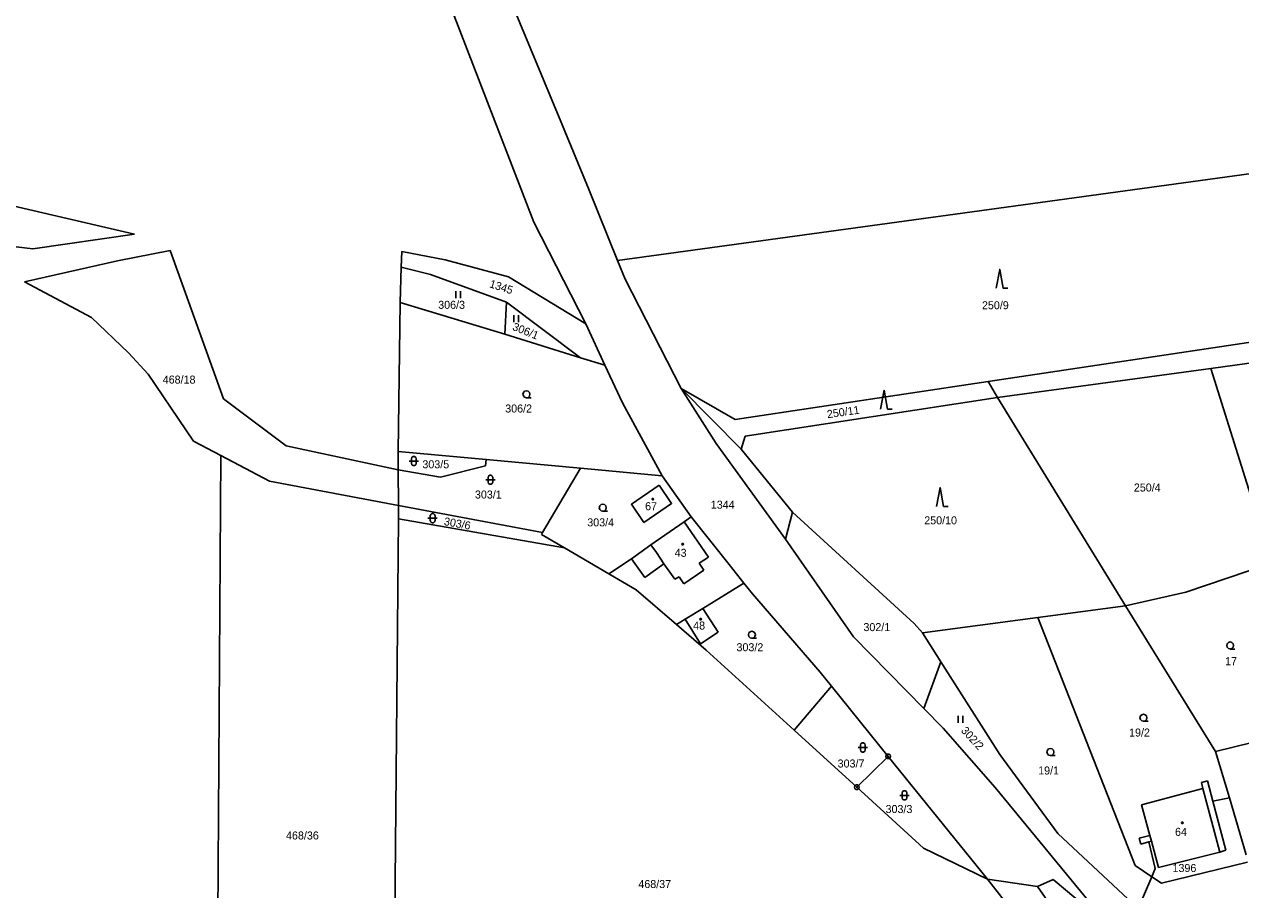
# Model space of a CAD drawing. Extents: x -845995 to -842497, y -1063614 to -1059680.
# Drawn here: x -844799.8 to -844541.5, y -1061389.6 to -1061205.9 of the extents above; entities that cross this region are included whole.
import ezdxf

# ---------------------------------------------------------------- set-up
doc = ezdxf.new("R2010")
doc.units = 0
for name, color, linetype in [('KN_HRANICE', 7, 'Continuous'), ('KN_KULTURY', 7, 'Continuous'), ('KN_MEZNIKY', 7, 'Continuous'), ('KN_PARCELY', 7, 'Continuous'), ('KN_SLUCKY', 7, 'Continuous'), ('KN_STAVEBNI', 7, 'Continuous')]:
    doc.layers.add(name, color=color, linetype=linetype)

# ---------------------------------------------------------------- blocks, each defined once
blk = doc.blocks.new('304')
blk.add_lwpolyline([(0, 0), (-0.38, 0.1), (-0.65, 0.37), (-0.75, 0.74), (-0.65, 1.11), (-0.38, 1.38), (-0.01, 1.48), (0.36, 1.38), (0.63, 1.11), (0.73, 0.73), (0.63, 0.35), (0.36, 0.08), (-0.02, -0.02), (0.98, -0.02)])
blk = doc.blocks.new('306')
for p, q in [((-0.5, 1.5), (-0.5, 0)), ((0.5, 0), (0.5, 1.5))]:
    blk.add_line(p, q)
blk = doc.blocks.new('308')
blk.add_lwpolyline([(-0.75, 0), (0, 4), (0.75, 0), (1.75, 0)])
blk = doc.blocks.new('316')
for points in [[(-1, 1), (0.27, 1), (1, 1)], [(-0.5, 1.5), (-0.4, 1.79), (-0.15, 1.97), (0.16, 1.97), (0.41, 1.79), (0.51, 1.5), (0.51, 0.5), (0.41, 0.21), (0.16, 0.03), (-0.15, 0.03), (-0.4, 0.21), (-0.5, 0.5), (-0.5, 1.5)]]:
    blk.add_lwpolyline(points)
blk = doc.blocks.new('105')
blk.add_line((-0.12, 0), (0.12, 0))
blk.add_lwpolyline([(0.15, 0.48), (0.4, 0.3), (0.5, 0.01), (0.4, -0.28), (0.15, -0.46), (-0.16, -0.46), (-0.41, -0.28), (-0.51, 0.01), (-0.41, 0.3), (-0.16, 0.48), (0.15, 0.48)])
blk = doc.blocks.new('402')
blk.add_lwpolyline([(0.09, 0.15), (0.18, 0), (0.09, -0.15), (-0.09, -0.15), (-0.18, 0), (-0.09, 0.15), (0.09, 0.15)])

msp = doc.modelspace()

# ---------------------------------------------------------------- linework, layer by layer
at = {"layer": 'KN_HRANICE'}
for p, q in [((-844720.73, -1061172.52), (-844691.6, -1061247.89)), ((-844685.56, -1061227.38), (-844703.99, -1061182.85)), ((-844679.88, -1061241.1), (-844685.56, -1061227.38)), ((-844673.82, -1061256.03), (-844523.56, -1061235.4)), ((-844679.88, -1061241.1), (-844673.82, -1061256.03)), ((-844776.42, -1061250.39), (-844804.1, -1061244)), ((-844852.01, -1061247.02), (-844797.97, -1061253.52)), ((-844691.6, -1061247.89), (-844680.59, -1061269.45)), ((-844797.97, -1061253.52), (-844776.42, -1061250.39)), ((-844780.02, -1061256.12), (-844768.84, -1061253.9)), ((-844768.84, -1061253.9), (-844757.5, -1061285.36)), ((-844719.67, -1061254.09), (-844719.77, -1061257.41)), ((-844710.46, -1061255.86), (-844719.67, -1061254.09)), ((-844799.79, -1061260.56), (-844780.02, -1061256.12)), ((-844697.02, -1061259.49), (-844710.46, -1061255.86)), ((-844673.82, -1061256.03), (-844672.21, -1061260)), ((-844719.77, -1061257.41), (-844719.98, -1061264.93)), ((-844713.56, -1061258.96), (-844719.77, -1061257.41)), ((-844697.4, -1061264.85), (-844713.56, -1061258.96)), ((-844680.59, -1061269.45), (-844697.02, -1061259.49)), ((-844785.52, -1061268.09), (-844799.79, -1061260.56)), ((-844672.21, -1061260), (-844660.3, -1061283.17)), ((-844719.98, -1061264.93), (-844720.4, -1061296.53)), ((-844719.98, -1061264.93), (-844697.8, -1061271.68)), ((-844697.4, -1061264.85), (-844697.8, -1061271.68)), ((-844681.7, -1061276.68), (-844697.4, -1061264.85)), ((-844777.71, -1061275.61), (-844785.52, -1061268.09)), ((-844680.59, -1061269.45), (-844676.52, -1061278.21)), ((-844697.8, -1061271.68), (-844681.7, -1061276.68)), ((-844595.18, -1061281.72), (-844522.5, -1061270.83)), ((-844547.89, -1061278.94), (-844509.56, -1061273.56)), ((-844773.47, -1061280.17), (-844777.71, -1061275.61)), ((-844676.52, -1061278.21), (-844681.7, -1061276.68)), ((-844773.47, -1061280.17), (-844763.91, -1061294.34)), ((-844676.52, -1061278.21), (-844672.78, -1061286.23)), ((-844547.89, -1061278.94), (-844593.18, -1061285.1)), ((-844534.95, -1061320.21), (-844547.89, -1061278.94)), ((-844648.86, -1061289.77), (-844595.18, -1061281.72)), ((-844593.18, -1061285.1), (-844595.18, -1061281.72)), ((-844757.5, -1061285.36), (-844744.19, -1061295.34)), ((-844648.86, -1061289.77), (-844660.3, -1061283.17)), ((-844660.3, -1061283.17), (-844647.58, -1061296.05)), ((-844646.76, -1061293.3), (-844593.18, -1061285.1)), ((-844593.18, -1061285.1), (-844565.97, -1061329.33)), ((-844672.78, -1061286.23), (-844664.39, -1061301.73)), ((-844647.58, -1061296.05), (-844646.76, -1061293.3)), ((-844763.91, -1061294.34), (-844758.07, -1061297.42)), ((-844744.19, -1061295.34), (-844720.45, -1061300.43)), ((-844759.29, -1061483.09), (-844758.07, -1061297.42)), ((-844758.07, -1061297.42), (-844747.75, -1061302.86)), ((-844720.45, -1061300.43), (-844720.4, -1061296.53)), ((-844701.72, -1061298.26), (-844720.4, -1061296.53)), ((-844701.87, -1061299.6), (-844701.72, -1061298.26)), ((-844701.72, -1061298.26), (-844681.7, -1061300.12)), ((-844636.7, -1061309.42), (-844647.58, -1061296.05)), ((-844720.45, -1061300.43), (-844711.43, -1061302.02)), ((-844720.45, -1061300.43), (-844720.38, -1061308)), ((-844711.43, -1061302.02), (-844701.87, -1061299.6)), ((-844681.7, -1061300.12), (-844689.75, -1061313.76)), ((-844681.7, -1061300.12), (-844664.39, -1061301.73)), ((-844747.75, -1061302.86), (-844720.38, -1061308)), ((-844664.39, -1061301.73), (-844658.2, -1061310.45)), ((-844720.38, -1061308), (-844720.36, -1061310.83)), ((-844720.38, -1061308), (-844689.75, -1061313.76)), ((-844720.36, -1061310.83), (-844721.83, -1061477.08)), ((-844720.36, -1061310.83), (-844685.12, -1061317)), ((-844659.68, -1061311.49), (-844666.75, -1061316.38)), ((-844659.68, -1061311.49), (-844658.2, -1061310.45)), ((-844650.16, -1061320.55), (-844658.2, -1061310.45)), ((-844636.7, -1061309.42), (-844638.21, -1061315.18)), ((-844610.86, -1061333.04), (-844636.7, -1061309.42)), ((-844689.75, -1061313.76), (-844689.98, -1061314.15)), ((-844685.12, -1061317), (-844689.98, -1061314.15)), ((-844670.88, -1061319.31), (-844666.75, -1061316.38)), ((-844638.21, -1061315.18), (-844623.75, -1061335.89)), ((-844675.67, -1061322.54), (-844685.12, -1061317)), ((-844675.67, -1061322.54), (-844670.88, -1061319.31)), ((-844646.99, -1061324.49), (-844650.16, -1061320.55)), ((-844553.2, -1061326.42), (-844534.95, -1061320.21)), ((-844669.9, -1061325.92), (-844675.67, -1061322.54)), ((-844661.35, -1061333.29), (-844669.9, -1061325.92)), ((-844655.73, -1061329.85), (-844646.99, -1061324.49)), ((-844645.22, -1061326.74), (-844646.99, -1061324.49)), ((-844645.22, -1061326.74), (-844630.82, -1061343.42)), ((-844565.97, -1061329.33), (-844553.2, -1061326.42)), ((-844584.6, -1061331.79), (-844565.97, -1061329.33)), ((-844565.97, -1061329.33), (-844546.85, -1061360.21)), ((-844655.73, -1061329.85), (-844659.51, -1061332.16)), ((-844655.73, -1061329.85), (-844652.47, -1061334.93)), ((-844609.09, -1061335.03), (-844584.6, -1061331.79)), ((-844584.6, -1061331.79), (-844563.96, -1061384.43)), ((-844661.35, -1061333.29), (-844659.51, -1061332.16)), ((-844655.01, -1061338.74), (-844661.35, -1061333.29)), ((-844659.51, -1061332.16), (-844656.2, -1061337.41)), ((-844609.09, -1061335.03), (-844610.86, -1061333.04)), ((-844652.47, -1061334.93), (-844656.2, -1061337.41)), ((-844623.75, -1061335.89), (-844608.78, -1061351.11)), ((-844609.09, -1061335.03), (-844605.17, -1061341.19)), ((-844636.31, -1061355.71), (-844655.01, -1061338.74)), ((-844608.78, -1061351.11), (-844605.17, -1061341.19)), ((-844605.17, -1061341.19), (-844592.68, -1061360.84)), ((-844630.82, -1061343.42), (-844628.4, -1061346.39)), ((-844628.4, -1061346.39), (-844636.31, -1061355.71)), ((-844628.4, -1061346.39), (-844616.36, -1061361.27)), ((-844608.78, -1061351.11), (-844604.71, -1061355.25)), ((-844604.71, -1061355.25), (-844593.67, -1061367.85)), ((-844546.85, -1061360.21), (-844527.05, -1061355.32)), ((-844623.03, -1061367.82), (-844636.31, -1061355.71)), ((-844546.85, -1061360.21), (-844543.93, -1061370.06)), ((-844616.36, -1061361.27), (-844623.03, -1061367.82)), ((-844616.36, -1061361.27), (-844595.28, -1061387.31)), ((-844592.68, -1061360.84), (-844580.38, -1061377.63)), ((-844608.89, -1061380.73), (-844623.03, -1061367.82)), ((-844593.67, -1061367.85), (-844569.16, -1061397.58)), ((-844549.56, -1061368.12), (-844562.59, -1061371.56)), ((-844548.55, -1061366.46), (-844549.86, -1061366.8)), ((-844549.86, -1061366.8), (-844549.56, -1061368.12)), ((-844547.43, -1061370.75), (-844548.55, -1061366.46)), ((-844543.93, -1061370.06), (-844547.43, -1061370.75)), ((-844544.69, -1061381.19), (-844547.43, -1061370.75)), ((-844543.93, -1061370.06), (-844540.35, -1061382.16)), ((-844562.59, -1061371.56), (-844560.8, -1061378.03)), ((-844580.38, -1061377.63), (-844563.31, -1061393.54)), ((-844560.8, -1061378.03), (-844563.09, -1061378.63)), ((-844563.09, -1061378.63), (-844562.74, -1061379.91)), ((-844608.89, -1061380.73), (-844595.28, -1061387.31)), ((-844562.74, -1061379.91), (-844561.01, -1061379.42)), ((-844561.01, -1061379.42), (-844560.49, -1061379.3)), ((-844559.66, -1061385.06), (-844561.01, -1061379.42)), ((-844560.49, -1061379.3), (-844558.97, -1061384.88)), ((-844545.97, -1061381.6), (-844544.69, -1061381.19)), ((-844558.97, -1061384.88), (-844545.97, -1061381.6)), ((-844558.34, -1061388.2), (-844540.07, -1061383.72)), ((-844563.96, -1061384.43), (-844560.41, -1061386.81)), ((-844560.41, -1061386.81), (-844559.66, -1061385.06)), ((-844580.08, -1061406.78), (-844595.28, -1061387.31)), ((-844563.31, -1061393.54), (-844560.41, -1061386.81)), ((-844560.41, -1061386.81), (-844558.34, -1061388.2))]:
    msp.add_line(p, q, dxfattribs=at)
msp.add_lwpolyline([(-844665.01, -1061303.73), (-844670.88, -1061307.77), (-844668.23, -1061311.61), (-844662.36, -1061307.59)], close=True, dxfattribs=at)
at = {"layer": 'KN_SLUCKY'}
for p, q in [((-844660.3, -1061283.17), (-844652.9, -1061294.84)), ((-844652.9, -1061294.84), (-844638.21, -1061315.18)), ((-844654.51, -1061319.01), (-844659.68, -1061311.49)), ((-844665.6, -1061318.02), (-844666.75, -1061316.38)), ((-844665.6, -1061318.02), (-844664, -1061320.38)), ((-844656.51, -1061320.27), (-844654.51, -1061319.01)), ((-844668.06, -1061323.31), (-844670.88, -1061319.31)), ((-844664, -1061320.38), (-844668.06, -1061323.31)), ((-844664, -1061320.38), (-844661.66, -1061323.63)), ((-844659.79, -1061324.63), (-844655.51, -1061321.76)), ((-844655.51, -1061321.76), (-844656.51, -1061320.27)), ((-844661.66, -1061323.63), (-844660.79, -1061323.13)), ((-844660.79, -1061323.13), (-844659.79, -1061324.63)), ((-844549.56, -1061368.12), (-844545.97, -1061381.6)), ((-844560.8, -1061378.03), (-844560.49, -1061379.3)), ((-844584.67, -1061388.89), (-844595.28, -1061387.31)), ((-844581.36, -1061387.39), (-844584.67, -1061388.89)), ((-844563.06, -1061419.45), (-844584.67, -1061388.89)), ((-844569.16, -1061397.58), (-844581.36, -1061387.39))]:
    msp.add_line(p, q, dxfattribs=at)
at = {"layer": 'KN_STAVEBNI'}
for p, q in [((-844659.68, -1061311.49), (-844666.75, -1061316.38)), ((-844654.51, -1061319.01), (-844659.68, -1061311.49)), ((-844665.6, -1061318.02), (-844666.75, -1061316.38)), ((-844665.6, -1061318.02), (-844664, -1061320.38)), ((-844656.51, -1061320.27), (-844654.51, -1061319.01)), ((-844664, -1061320.38), (-844661.66, -1061323.63)), ((-844659.79, -1061324.63), (-844655.51, -1061321.76)), ((-844655.51, -1061321.76), (-844656.51, -1061320.27)), ((-844661.66, -1061323.63), (-844660.79, -1061323.13)), ((-844660.79, -1061323.13), (-844659.79, -1061324.63)), ((-844655.73, -1061329.85), (-844659.51, -1061332.16)), ((-844655.73, -1061329.85), (-844652.47, -1061334.93)), ((-844659.51, -1061332.16), (-844656.2, -1061337.41)), ((-844652.47, -1061334.93), (-844656.2, -1061337.41)), ((-844549.56, -1061368.12), (-844562.59, -1061371.56)), ((-844549.56, -1061368.12), (-844545.97, -1061381.6)), ((-844562.59, -1061371.56), (-844560.8, -1061378.03)), ((-844560.8, -1061378.03), (-844560.49, -1061379.3)), ((-844560.49, -1061379.3), (-844558.97, -1061384.88)), ((-844558.97, -1061384.88), (-844545.97, -1061381.6))]:
    msp.add_line(p, q, dxfattribs=at)
msp.add_lwpolyline([(-844665.01, -1061303.73), (-844670.88, -1061307.77), (-844668.23, -1061311.61), (-844662.36, -1061307.59)], close=True, dxfattribs=at)

# ---------------------------------------------------------------- block references
at = {"layer": 'KN_KULTURY'}
for name, p in [('308', (-844592.69, -1061261.92)), ('306', (-844707.69, -1061264.01)), ('306', (-844695.34, -1061269.11)), ('304', (-844693.19, -1061285.14)), ('308', (-844617.25, -1061287.57)), ('316', (-844717.11, -1061299.59)), ('316', (-844700.84, -1061303.55)), ('308', (-844605.36, -1061308.21)), ('304', (-844676.96, -1061309.22)), ('402', (-844666.36, -1061306.65)), ('316', (-844713.11, -1061311.72)), ('402', (-844660, -1061316.24)), ('402', (-844656.2, -1061332.17)), ('304', (-844645.31, -1061336.18)), ('304', (-844543.75, -1061338.47)), ('306', (-844600.99, -1061354.13)), ('304', (-844562.17, -1061353.8)), ('316', (-844621.77, -1061360.38)), ('304', (-844581.92, -1061361.08)), ('316', (-844612.9, -1061370.55)), ('402', (-844553.93, -1061375.35))]:
    msp.add_blockref(name, p, dxfattribs=at)
at = {"layer": 'KN_MEZNIKY'}
for p in [(-844616.36, -1061361.27), (-844623.03, -1061367.82)]:
    msp.add_blockref('105', p, dxfattribs=at)

# ---------------------------------------------------------------- texts
at = {"layer": 'KN_PARCELY'}
for s, rotation, p in [('1345', 342.228, (-844701.19, -1061261.66)), ('306/1', 338.045, (-844696.31, -1061270.7)), ('250/11', 8.136, (-844629.25, -1061289.5)), ('303/6', 349.733, (-844710.81, -1061312.16)), ('302/2', 312.606, (-844601.03, -1061355.89))]:
    msp.add_text(s, height=1.7, rotation=rotation, dxfattribs=at).set_placement(p)
for s, p in [('306/3', (-844711.92, -1061266.27)), ('250/9', (-844596.46, -1061266.36)), ('468/18', (-844770.41, -1061282.14)), ('306/2', (-844697.69, -1061288.28)), ('303/5', (-844715.28, -1061300.12)), ('250/4', (-844564.21, -1061305.05)), ('303/1', (-844704.12, -1061306.54)), ('67', (-844667.99, -1061309.02)), ('1344', (-844654.04, -1061308.69)), ('303/4', (-844680.27, -1061312.45)), ('250/10', (-844608.72, -1061312.02)), ('43', (-844661.71, -1061318.91)), ('48', (-844657.78, -1061334.35)), ('302/1', (-844621.63, -1061334.68)), ('303/2', (-844648.58, -1061338.95)), ('17', (-844544.84, -1061341.91)), ('19/2', (-844565.23, -1061357.06)), ('303/7', (-844627.11, -1061363.63)), ('19/1', (-844584.53, -1061365.11)), ('303/3', (-844616.93, -1061373.3)), ('468/36', (-844744.23, -1061378.91)), ('64', (-844555.47, -1061378.14)), ('1396', (-844556, -1061385.82)), ('468/37', (-844669.42, -1061389.22))]:
    msp.add_text(s, height=1.7, dxfattribs=at).set_placement(p)

doc.saveas('drawing.dxf')
